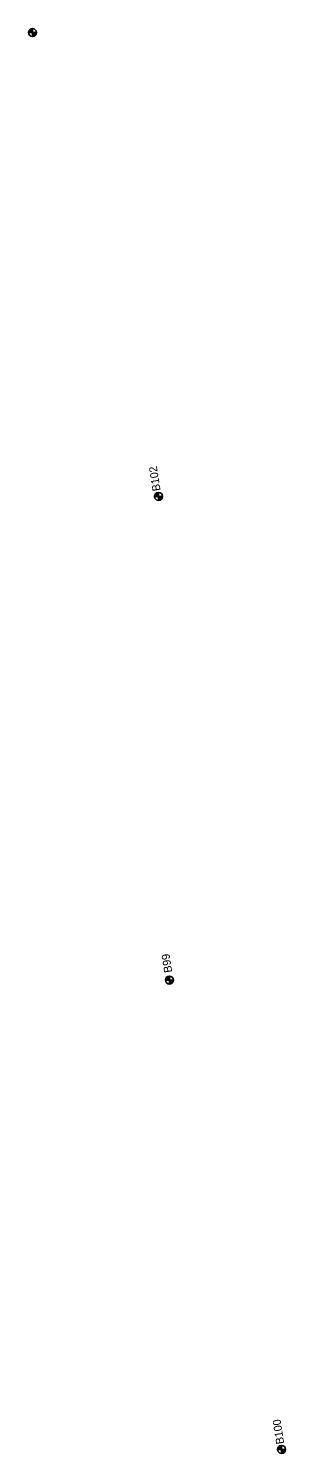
# Model space of a CAD drawing. Extents: x 335726 to 369746, y 119154 to 200788.
# Drawn here: x 355686 to 356007, y 182421 to 184202 of the extents above; entities that cross this region are included whole.
import ezdxf

# ---------------------------------------------------------------- set-up
doc = ezdxf.new("R2010")
doc.units = 0
for name, color, linetype in [('E_SOIL_BORE1 [KAPUR_CADDS_LEVELS]', 7, 'Continuous'), ('E_SOIL_BORE2 [KAPUR_CADDS_LEVELS]', 7, 'Continuous'), ('P_MARK', 7, 'Continuous')]:
    doc.layers.add(name, color=color, linetype=linetype)

msp = doc.modelspace()

# ---------------------------------------------------------------- linework, layer by layer
at = {"layer": 'P_MARK'}
for p, q in [((355685.7, 184196.6), (355695.7, 184196.6)), ((355690.7, 184201.6), (355690.7, 184191.6)), ((355843.4, 183616.8), (355853.4, 183616.8)), ((355848.4, 183621.8), (355848.4, 183611.8)), ((355857, 183012.4), (355867, 183012.4)), ((355862, 183017.4), (355862, 183007.4)), ((355997.3, 182425.8), (356007.3, 182425.8)), ((356002.3, 182430.8), (356002.3, 182420.8))]:
    msp.add_line(p, q, dxfattribs=at)
for centre in [(355690.7, 184196.6), (355848.4, 183616.8), (355862, 183012.4), (356002.3, 182425.8)]:
    msp.add_circle(centre, 5, dxfattribs=at)
for centre, radius, start, end in [((355690.7, 184196.6), 4.5, 89.9869, 179.9869), ((355690.7, 184196.6), 4, 89.9869, 179.9869), ((355690.7, 184196.6), 3.5, 89.9869, 179.9869), ((355690.7, 184196.6), 3, 89.9869, 179.9869), ((355690.7, 184196.6), 2.5, 89.9869, 179.9869), ((355690.7, 184196.6), 2, 89.9869, 179.9869), ((355690.7, 184196.6), 1.5, 89.9869, 179.9869), ((355690.7, 184196.6), 1, 89.9869, 179.9869), ((355690.7, 184196.6), 0.5, 89.9869, 179.9869), ((355690.7, 184196.6), 4.5, 269.9869, 359.9869), ((355690.7, 184196.6), 4, 269.9869, 359.9869), ((355690.7, 184196.6), 3.5, 269.9869, 359.9869), ((355690.7, 184196.6), 3, 269.9869, 359.9869), ((355690.7, 184196.6), 2.5, 269.9869, 359.9869), ((355690.7, 184196.6), 2, 269.9869, 359.9869), ((355690.7, 184196.6), 1.5, 269.9869, 359.9869), ((355690.7, 184196.6), 1, 269.9869, 359.9869), ((355690.7, 184196.6), 0.5, 269.9869, 359.9869), ((355848.4, 183616.8), 4.5, 89.9869, 179.9869), ((355848.4, 183616.8), 4, 89.9869, 179.9869), ((355848.4, 183616.8), 3.5, 89.9869, 179.9869), ((355848.4, 183616.8), 3, 89.9869, 179.9869), ((355848.4, 183616.8), 2.5, 89.9869, 179.9869), ((355848.4, 183616.8), 2, 89.9869, 179.9869), ((355848.4, 183616.8), 1.5, 89.9869, 179.9869), ((355848.4, 183616.8), 1, 89.9869, 179.9869), ((355848.4, 183616.8), 0.5, 89.9869, 179.9869), ((355848.4, 183616.8), 4.5, 269.9869, 359.9869), ((355848.4, 183616.8), 4, 269.9869, 359.9869), ((355848.4, 183616.8), 3.5, 269.9869, 359.9869), ((355848.4, 183616.8), 3, 269.9869, 359.9869), ((355848.4, 183616.8), 2.5, 269.9869, 359.9869), ((355848.4, 183616.8), 2, 269.9869, 359.9869), ((355848.4, 183616.8), 1.5, 269.9869, 359.9869), ((355848.4, 183616.8), 1, 269.9869, 359.9869), ((355848.4, 183616.8), 0.5, 269.9869, 359.9869), ((355862, 183012.4), 4.5, 89.9869, 179.9869), ((355862, 183012.4), 4, 89.9869, 179.9869), ((355862, 183012.4), 3.5, 89.9869, 179.9869), ((355862, 183012.4), 3, 89.9869, 179.9869), ((355862, 183012.4), 2.5, 89.9869, 179.9869), ((355862, 183012.4), 2, 89.9869, 179.9869), ((355862, 183012.4), 1.5, 89.9869, 179.9869), ((355862, 183012.4), 1, 89.9869, 179.9869), ((355862, 183012.4), 0.5, 89.9869, 179.9869), ((355862, 183012.4), 4.5, 269.9869, 359.9869), ((355862, 183012.4), 4, 269.9869, 359.9869), ((355862, 183012.4), 3.5, 269.9869, 359.9869), ((355862, 183012.4), 3, 269.9869, 359.9869), ((355862, 183012.4), 2.5, 269.9869, 359.9869), ((355862, 183012.4), 2, 269.9869, 359.9869), ((355862, 183012.4), 1.5, 269.9869, 359.9869), ((355862, 183012.4), 1, 269.9869, 359.9869), ((355862, 183012.4), 0.5, 269.9869, 359.9869), ((356002.3, 182425.8), 4.5, 89.9869, 179.9869), ((356002.3, 182425.8), 4, 89.9869, 179.9869), ((356002.3, 182425.8), 3.5, 89.9869, 179.9869), ((356002.3, 182425.8), 3, 89.9869, 179.9869), ((356002.3, 182425.8), 2.5, 89.9869, 179.9869), ((356002.3, 182425.8), 2, 89.9869, 179.9869), ((356002.3, 182425.8), 1.5, 89.9869, 179.9869), ((356002.3, 182425.8), 1, 89.9869, 179.9869), ((356002.3, 182425.8), 0.5, 89.9869, 179.9869), ((356002.3, 182425.8), 4.5, 269.9869, 359.9869), ((356002.3, 182425.8), 4, 269.9869, 359.9869), ((356002.3, 182425.8), 3.5, 269.9869, 359.9869), ((356002.3, 182425.8), 3, 269.9869, 359.9869), ((356002.3, 182425.8), 2.5, 269.9869, 359.9869), ((356002.3, 182425.8), 2, 269.9869, 359.9869), ((356002.3, 182425.8), 1.5, 269.9869, 359.9869), ((356002.3, 182425.8), 1, 269.9869, 359.9869), ((356002.3, 182425.8), 0.5, 269.9869, 359.9869)]:
    msp.add_arc(centre, radius, start, end, dxfattribs=at)

# ---------------------------------------------------------------- texts
at = {"layer": 'E_SOIL_BORE1 [KAPUR_CADDS_LEVELS]'}
msp.add_text('B102', height=10, rotation=98.957, dxfattribs=at).set_placement((355851, 183624.3))
at = {"layer": 'E_SOIL_BORE2 [KAPUR_CADDS_LEVELS]'}
for s, p in [('B99', (355865.6, 183022.4)), ('B100', (356005.7, 182433.2))]:
    msp.add_text(s, height=10, rotation=98.957, dxfattribs=at).set_placement(p)

doc.saveas('drawing.dxf')
